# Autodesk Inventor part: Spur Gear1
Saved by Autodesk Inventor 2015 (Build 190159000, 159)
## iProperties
Created: 2014-06
Part Number: Spur Gear1
Material: Steel
Document SubType Name: Modeling
Designer: User
Categories: <?xml version="1.0" encoding="UTF-16"?> <MemberInstance><Categories><FamilyTemplate><FamilyTemplateParameter ValueType="xs:double" Id="1" ObjectReferenceKey="da
Density: 1 g/cm^3
Appearance: Steel
CustomPartVersion: 1
Author: User
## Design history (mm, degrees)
sketch "Sketch1"
  geometry: C1 r 8.792 at (0, 0)
  constraints: 1 centre point
  dimensions: "d0" = 17.5849 diameter of C1 (= da_da)
extrude "Extrusion1" new body sketch "Sketch1" distance "d1" = 4 (= da_b); taper "d2" = 0 deg
workplane "Work Plane2"
sketch "Sketch2"
  geometry: C1 r 8.792 at (0, 0) reference; C2 r 8 at (0, 0)
  constraints: 1 centre point, 1 coincident
  dimensions: "d3" = 16 diameter of C2 (= da_dw)
feature "Pitch Diameter" sketch "Sketch2" dims "d4" = 10, "d5" = 0
workplane "Work Plane8"
workplane "Work Plane9"
feature "Spur Gear" dims "da_b" = 4, "da_d" = 15.66489, "da_aw" = 16, "da_da" = 17.5849, "da_df" = 14.0151, "da_dw" = 16, angle "da_beta" = 40 deg, "da_lefttooth" = 10, "da_righttooth" = 0
body "Solid1"
body "Srf1"
other parameters: "d16" = 16 (= da_aw), "d17" = 0, "d34" = 12 deg (computed from da_z), "d39" = 0, "d41" = 0, "d43" = 16 (= da_aw), "d46" = 16 (= da_aw), "d47" = 0, "d48" = 0
